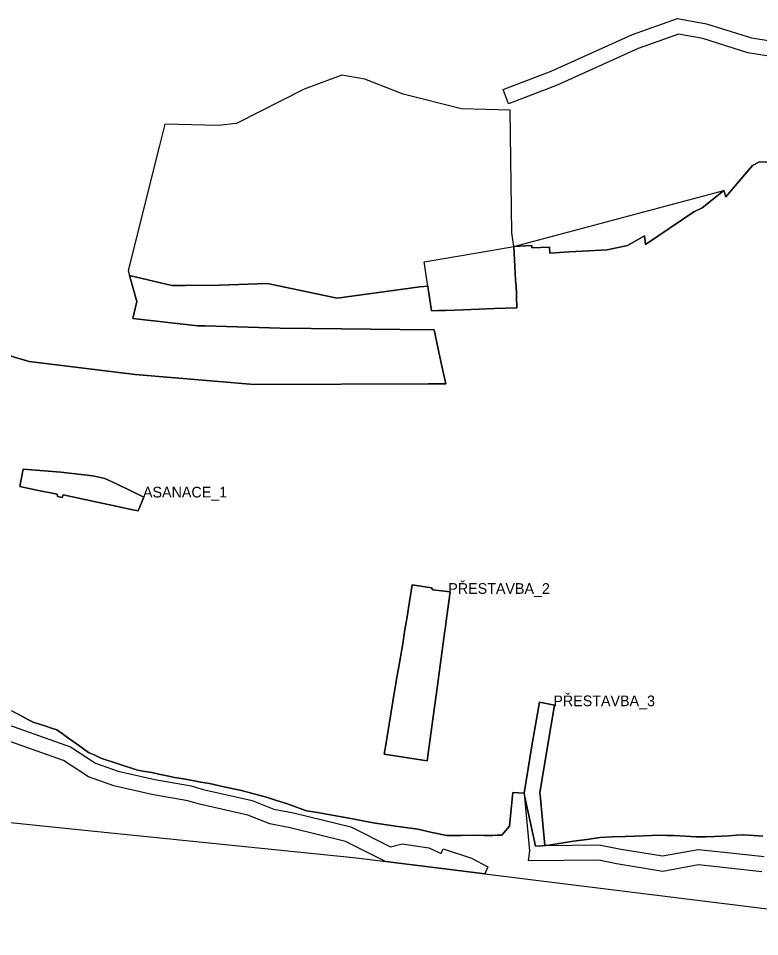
# Model space of a CAD drawing. Extents: x -521621 to -516761, y -1190184 to -1184927.
# Drawn here: x -519643 to -519157, y -1187565 to -1186963 of the extents above; entities that cross this region are included whole.
import ezdxf

# ---------------------------------------------------------------- set-up
doc = ezdxf.new("R2010")
doc.units = 0
for name, color, linetype in [('asanace_n', 7, 'Continuous'), ('hran_SZUO_P-s', 7, 'Continuous'), ('HZU_P_s', 7, 'Continuous'), ('Implicitní', 7, 'Continuous'), ('prestavba_n', 7, 'Continuous'), ('zastavitelne plochy', 7, 'Continuous')]:
    doc.layers.add(name, color=color, linetype=linetype)

msp = doc.modelspace()

# ---------------------------------------------------------------- linework, layer by layer
at = {"layer": 'asanace_n'}
msp.add_lwpolyline([(-519640.08, -1187258.64), (-519642.17, -1187270.06), (-519631.16, -1187272.32), (-519617.71, -1187275.08), (-519617.55, -1187276.62), (-519614.54, -1187277.08), (-519613.85, -1187275.54), (-519596.49, -1187279.24), (-519581.23, -1187282.49), (-519568.13, -1187285.28), (-519564.62, -1187286.03), (-519560.92, -1187276.93), (-519578.86, -1187268.28), (-519586.38, -1187264.66), (-519594.25, -1187262.96), (-519615.32, -1187260.57), (-519640.08, -1187258.64)], dxfattribs=at)
at = {"layer": 'hran_SZUO_P-s'}
for points in [[(-519157.33, -1187057.16), (-519161.95, -1187059.54)], [(-519095.24, -1187058.86), (-519157.33, -1187057.16)], [(-519161.95, -1187059.54), (-519179.53, -1187080.02)], [(-519180.77, -1187076), (-519188.69, -1187082.32)], [(-519179.53, -1187080.02), (-519180.77, -1187076)], [(-519194.92, -1187087.29), (-519200.56, -1187089.87)], [(-519188.69, -1187082.32), (-519194.92, -1187087.29)], [(-519200.56, -1187089.87), (-519232.12, -1187111.29)], [(-519232.7, -1187105.55), (-519243.91, -1187111.93)], [(-519232.12, -1187111.29), (-519232.7, -1187105.55)], [(-519306.72, -1187112.05), (-519318.38, -1187112.72)], [(-519318.38, -1187112.72), (-519317.33, -1187134.43)], [(-519306.63, -1187113.6), (-519306.72, -1187112.05)], [(-519295.05, -1187113.11), (-519306.63, -1187113.6)], [(-519294.77, -1187116.93), (-519295.05, -1187113.11)], [(-519282.06, -1187116.19), (-519294.77, -1187116.93)], [(-519269.34, -1187115.44), (-519282.06, -1187116.19)], [(-519257.18, -1187114.73), (-519269.34, -1187115.44)], [(-519243.91, -1187111.93), (-519257.18, -1187114.73)], [(-519542.51, -1187138.24), (-519570.28, -1187131.58)], [(-519570.28, -1187131.58), (-519565.59, -1187148.78)], [(-519317.33, -1187134.43), (-519317.16, -1187136.78), (-519316.98, -1187139.13)], [(-519533.88, -1187138.14), (-519542.51, -1187138.24)], [(-519511.41, -1187137.88), (-519533.88, -1187138.14)], [(-519479.95, -1187136.97), (-519511.41, -1187137.88)], [(-519439.45, -1187145.43), (-519479.95, -1187136.97)], [(-519379.97, -1187139), (-519434.32, -1187146.5)], [(-519374.79, -1187138.62), (-519379.97, -1187139)], [(-519373.47, -1187147.63), (-519374.79, -1187138.62)], [(-519316.98, -1187139.13), (-519316.87, -1187140.66), (-519316.76, -1187142.18)], [(-519434.32, -1187146.5), (-519439.45, -1187145.43)], [(-519316.76, -1187142.18), (-519316.68, -1187145.05), (-519316.6, -1187147.92)], [(-519565.59, -1187148.78), (-519568.17, -1187159.87)], [(-519372.41, -1187154.85), (-519373.47, -1187147.63)], [(-519331.04, -1187153.34), (-519341.19, -1187153.71)], [(-519316.47, -1187152.81), (-519323.75, -1187153.08), (-519331.04, -1187153.34)], [(-519316.6, -1187147.92), (-519316.54, -1187150.36)], [(-519316.54, -1187150.36), (-519316.47, -1187152.81)], [(-519367.87, -1187154.69), (-519372.41, -1187154.85)], [(-519363.32, -1187154.52), (-519367.87, -1187154.69)], [(-519351.35, -1187154.08), (-519357.33, -1187154.3), (-519363.32, -1187154.52)], [(-519341.19, -1187153.71), (-519351.35, -1187154.08)], [(-519568.17, -1187159.87), (-519525.62, -1187164.56)], [(-519525.62, -1187164.56), (-519520.78, -1187164.7)], [(-519520.78, -1187164.7), (-519471.58, -1187166.09)], [(-519636.11, -1187188.04), (-519691.98, -1187171.68)], [(-519471.58, -1187166.09), (-519431.2, -1187166.58)], [(-519431.2, -1187166.58), (-519393.07, -1187167.04)], [(-519393.07, -1187167.04), (-519370.6, -1187167.23)], [(-519370.6, -1187167.23), (-519367.71, -1187180.87)], [(-519367.71, -1187180.87), (-519366.84, -1187184.99)], [(-519566.51, -1187196.52), (-519636.11, -1187188.04)], [(-519366.84, -1187184.99), (-519365.76, -1187190.07)], [(-519365.76, -1187190.07), (-519363.08, -1187202.74)], [(-519488.58, -1187203.01), (-519566.51, -1187196.52)], [(-519374.38, -1187202.7), (-519488.58, -1187203.01)], [(-519363.08, -1187202.74), (-519374.38, -1187202.7)], [(-519647.92, -1187416.82), (-519644.14, -1187418.84), (-519640.35, -1187420.87)], [(-519640.35, -1187420.87), (-519636.92, -1187422.71), (-519633.49, -1187424.54)], [(-519633.49, -1187424.54), (-519629.29, -1187425.87), (-519625.09, -1187427.2)], [(-519625.09, -1187427.2), (-519621.5, -1187428.34), (-519617.9, -1187429.48)], [(-519617.9, -1187429.48), (-519614.38, -1187432.01), (-519610.86, -1187434.53)], [(-519610.86, -1187434.53), (-519607.28, -1187437.09), (-519603.7, -1187439.66)], [(-519603.7, -1187439.66), (-519600.46, -1187442.02), (-519597.22, -1187444.37)], [(-519597.22, -1187444.37), (-519593.13, -1187446.22), (-519589.04, -1187448.07)], [(-519589.04, -1187448.07), (-519577.04, -1187451.97), (-519565.04, -1187455.87)], [(-519565.04, -1187455.87), (-519560.34, -1187456.72), (-519555.63, -1187457.56)], [(-519555.63, -1187457.56), (-519551.2, -1187458.53), (-519546.76, -1187459.49)], [(-519546.76, -1187459.49), (-519543.79, -1187460.11), (-519540.81, -1187460.73)], [(-519540.81, -1187460.73), (-519534.91, -1187461.73), (-519529.01, -1187462.73)], [(-519529.01, -1187462.73), (-519523.46, -1187463.74), (-519517.9, -1187464.74)], [(-519517.9, -1187464.74), (-519507.45, -1187467.06), (-519496.99, -1187469.37)], [(-519496.99, -1187469.37), (-519488.81, -1187471.49), (-519480.63, -1187473.61)], [(-519321.33, -1187492.71), (-519320.25, -1187481.6), (-519319.17, -1187470.49)], [(-519319.17, -1187470.49), (-519315.42, -1187470.81), (-519311.66, -1187471.13)], [(-519311.66, -1187471.13), (-519311.4, -1187472.37), (-519311.13, -1187473.61)], [(-519480.63, -1187473.61), (-519474.07, -1187475.74), (-519467.51, -1187477.86)], [(-519467.51, -1187477.86), (-519460.92, -1187480.22), (-519454.32, -1187482.57)], [(-519311.13, -1187473.61), (-519307.7, -1187489.7), (-519304.26, -1187505.78)], [(-519454.32, -1187482.57), (-519447.14, -1187483.77), (-519439.96, -1187484.96)], [(-519439.96, -1187484.96), (-519425.26, -1187487.74), (-519410.56, -1187490.51)], [(-519410.56, -1187490.51), (-519395.98, -1187492.59), (-519381.4, -1187494.68)], [(-519381.4, -1187494.68), (-519371.91, -1187496.73), (-519362.42, -1187498.77)], [(-519326.38, -1187498.54), (-519323.86, -1187495.62)], [(-519323.86, -1187495.62), (-519321.33, -1187492.71)], [(-519362.42, -1187498.77), (-519353.05, -1187498.69)], [(-519353.05, -1187498.69), (-519343.67, -1187498.61)], [(-519343.67, -1187498.61), (-519337.96, -1187498.69), (-519332.25, -1187498.77)], [(-519332.25, -1187498.77), (-519329.32, -1187498.66), (-519326.38, -1187498.54)], [(-519295.55, -1187505.13), (-519287.41, -1187503.86), (-519279.26, -1187502.6)], [(-519279.26, -1187502.6), (-519270.6, -1187501.33), (-519261.94, -1187500.07)], [(-519261.94, -1187500.07), (-519253.7, -1187499.74)], [(-519253.7, -1187499.74), (-519245.46, -1187499.41)], [(-519245.46, -1187499.41), (-519239.43, -1187499.15), (-519233.4, -1187498.89)], [(-519233.4, -1187498.89), (-519228.23, -1187498.74), (-519223.06, -1187498.58)], [(-519223.06, -1187498.58), (-519218.25, -1187498.72), (-519213.43, -1187498.85)], [(-519213.43, -1187498.85), (-519206.12, -1187499.23), (-519198.82, -1187499.6)], [(-519198.82, -1187499.6), (-519192.88, -1187499.56), (-519186.93, -1187499.51)], [(-519186.93, -1187499.51), (-519182.2, -1187499.2), (-519177.46, -1187498.89)], [(-519177.46, -1187498.89), (-519172.56, -1187498.66), (-519167.66, -1187498.42)], [(-519167.66, -1187498.42), (-519161.43, -1187498.86), (-519155.19, -1187499.3)], [(-519304.26, -1187505.78), (-519299.91, -1187505.46)], [(-519299.91, -1187505.46), (-519295.55, -1187505.13)]]:
    msp.add_lwpolyline(points, dxfattribs=at)
at = {"layer": 'HZU_P_s'}
for p, q in [((-519161.95, -1187059.54), (-519157.33, -1187057.16)), ((-519157.33, -1187057.16), (-519095.24, -1187058.86)), ((-519179.53, -1187080.02), (-519161.95, -1187059.54)), ((-519188.69, -1187082.32), (-519180.77, -1187076)), ((-519180.77, -1187076), (-519179.53, -1187080.02)), ((-519200.56, -1187089.87), (-519194.92, -1187087.29)), ((-519194.92, -1187087.29), (-519188.69, -1187082.32)), ((-519232.12, -1187111.29), (-519200.56, -1187089.87)), ((-519243.91, -1187111.93), (-519232.7, -1187105.55)), ((-519232.7, -1187105.55), (-519232.12, -1187111.29)), ((-519318.38, -1187112.72), (-519306.72, -1187112.05)), ((-519317.33, -1187134.43), (-519318.38, -1187112.72)), ((-519306.72, -1187112.05), (-519306.63, -1187113.6)), ((-519306.63, -1187113.6), (-519295.05, -1187113.11)), ((-519295.05, -1187113.11), (-519294.77, -1187116.93)), ((-519294.77, -1187116.93), (-519282.06, -1187116.19)), ((-519282.06, -1187116.19), (-519269.34, -1187115.44)), ((-519269.34, -1187115.44), (-519257.18, -1187114.73)), ((-519257.18, -1187114.73), (-519243.91, -1187111.93)), ((-519565.59, -1187148.78), (-519570.28, -1187131.58)), ((-519570.28, -1187131.58), (-519542.51, -1187138.24)), ((-519317.16, -1187136.78), (-519317.33, -1187134.43)), ((-519542.51, -1187138.24), (-519533.88, -1187138.14)), ((-519533.88, -1187138.14), (-519511.41, -1187137.88)), ((-519511.41, -1187137.88), (-519479.95, -1187136.97)), ((-519479.95, -1187136.97), (-519439.45, -1187145.43)), ((-519434.32, -1187146.5), (-519379.97, -1187139)), ((-519379.97, -1187139), (-519374.79, -1187138.62)), ((-519374.79, -1187138.62), (-519373.47, -1187147.63)), ((-519439.45, -1187145.43), (-519434.32, -1187146.5)), ((-519568.17, -1187159.87), (-519565.59, -1187148.78)), ((-519373.47, -1187147.63), (-519372.41, -1187154.85)), ((-519316.47, -1187152.81), (-519316.54, -1187150.36)), ((-519525.62, -1187164.56), (-519568.17, -1187159.87)), ((-519520.78, -1187164.7), (-519525.62, -1187164.56)), ((-519471.58, -1187166.09), (-519520.78, -1187164.7)), ((-519691.98, -1187171.68), (-519636.11, -1187188.04)), ((-519431.2, -1187166.58), (-519471.58, -1187166.09)), ((-519393.07, -1187167.04), (-519431.2, -1187166.58)), ((-519370.6, -1187167.23), (-519393.07, -1187167.04)), ((-519367.71, -1187180.87), (-519370.6, -1187167.23)), ((-519366.84, -1187184.99), (-519367.71, -1187180.87)), ((-519636.11, -1187188.04), (-519566.51, -1187196.52)), ((-519365.76, -1187190.07), (-519366.84, -1187184.99)), ((-519363.08, -1187202.74), (-519365.76, -1187190.07)), ((-519566.51, -1187196.52), (-519488.58, -1187203.01)), ((-519488.58, -1187203.01), (-519374.38, -1187202.7)), ((-519374.38, -1187202.7), (-519363.08, -1187202.74)), ((-519640.35, -1187420.87), (-519644.14, -1187418.84)), ((-519636.92, -1187422.71), (-519640.35, -1187420.87)), ((-519633.49, -1187424.54), (-519636.92, -1187422.71)), ((-519629.29, -1187425.87), (-519633.49, -1187424.54)), ((-519625.09, -1187427.2), (-519629.29, -1187425.87)), ((-519621.5, -1187428.34), (-519625.09, -1187427.2)), ((-519319.17, -1187470.49), (-519320.25, -1187481.6)), ((-519315.42, -1187470.81), (-519319.17, -1187470.49)), ((-519311.66, -1187471.13), (-519315.42, -1187470.81)), ((-519311.4, -1187472.37), (-519311.66, -1187471.13)), ((-519311.13, -1187473.61), (-519311.4, -1187472.37)), ((-519307.7, -1187489.7), (-519311.13, -1187473.61)), ((-519304.26, -1187505.78), (-519307.7, -1187489.7)), ((-519362.42, -1187498.77), (-519371.91, -1187496.73)), ((-519353.05, -1187498.69), (-519362.42, -1187498.77)), ((-519343.67, -1187498.61), (-519353.05, -1187498.69)), ((-519337.96, -1187498.69), (-519343.67, -1187498.61)), ((-519332.25, -1187498.77), (-519337.96, -1187498.69)), ((-519329.32, -1187498.66), (-519332.25, -1187498.77)), ((-519279.26, -1187502.6), (-519287.41, -1187503.86)), ((-519270.6, -1187501.33), (-519279.26, -1187502.6)), ((-519261.94, -1187500.07), (-519270.6, -1187501.33)), ((-519253.7, -1187499.74), (-519261.94, -1187500.07)), ((-519245.46, -1187499.41), (-519253.7, -1187499.74)), ((-519239.43, -1187499.15), (-519245.46, -1187499.41)), ((-519233.4, -1187498.89), (-519239.43, -1187499.15)), ((-519228.23, -1187498.74), (-519233.4, -1187498.89)), ((-519223.06, -1187498.58), (-519228.23, -1187498.74)), ((-519218.25, -1187498.72), (-519223.06, -1187498.58)), ((-519213.43, -1187498.85), (-519218.25, -1187498.72)), ((-519206.12, -1187499.23), (-519213.43, -1187498.85)), ((-519198.82, -1187499.6), (-519206.12, -1187499.23)), ((-519192.88, -1187499.56), (-519198.82, -1187499.6)), ((-519186.93, -1187499.51), (-519192.88, -1187499.56)), ((-519182.2, -1187499.2), (-519186.93, -1187499.51)), ((-519177.46, -1187498.89), (-519182.2, -1187499.2)), ((-519172.56, -1187498.66), (-519177.46, -1187498.89)), ((-519167.66, -1187498.42), (-519172.56, -1187498.66)), ((-519161.43, -1187498.86), (-519167.66, -1187498.42)), ((-519155.19, -1187499.3), (-519161.43, -1187498.86)), ((-519299.91, -1187505.46), (-519304.26, -1187505.78)), ((-519295.55, -1187505.13), (-519299.91, -1187505.46)), ((-519287.41, -1187503.86), (-519295.55, -1187505.13))]:
    msp.add_line(p, q, dxfattribs=at)
for points in [[(-519316.98, -1187139.13), (-519317.16, -1187136.78)], [(-519316.87, -1187140.66), (-519316.98, -1187139.13)], [(-519316.76, -1187142.18), (-519316.87, -1187140.66)], [(-519316.6, -1187147.92), (-519316.68, -1187145.05), (-519316.76, -1187142.18)], [(-519341.19, -1187153.71), (-519331.04, -1187153.34), (-519323.75, -1187153.08), (-519316.47, -1187152.81)], [(-519316.54, -1187150.36), (-519316.6, -1187147.92)], [(-519372.41, -1187154.85), (-519367.87, -1187154.69)], [(-519367.87, -1187154.69), (-519363.32, -1187154.52)], [(-519363.32, -1187154.52), (-519357.33, -1187154.3)], [(-519357.33, -1187154.3), (-519351.35, -1187154.08)], [(-519351.35, -1187154.08), (-519341.19, -1187153.71)], [(-519617.9, -1187429.48), (-519621.5, -1187428.34)], [(-519610.86, -1187434.53), (-519614.38, -1187432.01), (-519617.9, -1187429.48)], [(-519603.7, -1187439.66), (-519607.28, -1187437.09), (-519610.86, -1187434.53)], [(-519597.22, -1187444.37), (-519600.46, -1187442.02), (-519603.7, -1187439.66)], [(-519589.04, -1187448.07), (-519593.13, -1187446.22), (-519597.22, -1187444.37)], [(-519565.04, -1187455.87), (-519577.04, -1187451.97), (-519589.04, -1187448.07)], [(-519555.63, -1187457.56), (-519560.34, -1187456.72), (-519565.04, -1187455.87)], [(-519546.76, -1187459.49), (-519551.2, -1187458.53), (-519555.63, -1187457.56)], [(-519540.81, -1187460.73), (-519543.79, -1187460.11), (-519546.76, -1187459.49)], [(-519529.01, -1187462.73), (-519534.91, -1187461.73), (-519540.81, -1187460.73)], [(-519517.9, -1187464.74), (-519523.46, -1187463.74), (-519529.01, -1187462.73)], [(-519496.99, -1187469.37), (-519507.45, -1187467.06), (-519517.9, -1187464.74)], [(-519480.63, -1187473.61), (-519488.81, -1187471.49), (-519496.99, -1187469.37)], [(-519467.51, -1187477.86), (-519474.07, -1187475.74), (-519480.63, -1187473.61)], [(-519454.32, -1187482.57), (-519460.92, -1187480.22), (-519467.51, -1187477.86)], [(-519439.96, -1187484.96), (-519447.14, -1187483.77), (-519454.32, -1187482.57)], [(-519320.25, -1187481.6), (-519321.33, -1187492.71)], [(-519410.56, -1187490.51), (-519425.26, -1187487.74), (-519439.96, -1187484.96)], [(-519381.4, -1187494.68), (-519395.98, -1187492.59), (-519410.56, -1187490.51)], [(-519371.91, -1187496.73), (-519381.4, -1187494.68)], [(-519323.86, -1187495.62), (-519326.38, -1187498.54)], [(-519321.33, -1187492.71), (-519323.86, -1187495.62)], [(-519326.38, -1187498.54), (-519329.32, -1187498.66)]]:
    msp.add_lwpolyline(points, dxfattribs=at)
at = {"layer": 'Implicitní'}
for p, q in [((-519377.12, -1187122.72), (-519333.59, -1187115.31)), ((-519333.59, -1187115.31), (-519318.38, -1187112.72)), ((-519318.38, -1187112.72), (-519317.33, -1187134.43)), ((-519374.79, -1187138.62), (-519377.12, -1187122.72)), ((-519317.33, -1187134.43), (-519316.98, -1187139.13)), ((-519373.47, -1187147.63), (-519374.79, -1187138.62)), ((-519316.98, -1187139.13), (-519316.76, -1187142.18)), ((-519316.76, -1187142.18), (-519316.6, -1187147.92)), ((-519372.42, -1187154.83), (-519373.47, -1187147.63)), ((-519331.04, -1187153.34), (-519351.35, -1187154.08)), ((-519316.47, -1187152.81), (-519331.04, -1187153.34)), ((-519316.6, -1187147.92), (-519316.47, -1187152.81)), ((-519372.41, -1187154.85), (-519372.42, -1187154.83)), ((-519363.32, -1187154.52), (-519372.41, -1187154.85)), ((-519351.35, -1187154.08), (-519363.32, -1187154.52)), ((-519386.81, -1187345.32), (-519385.08, -1187334.48)), ((-519385.08, -1187334.48), (-519372.33, -1187336.38)), ((-519372.33, -1187336.38), (-519371.56, -1187337.62)), ((-519371.56, -1187337.62), (-519360.16, -1187339.01)), ((-519360.16, -1187339.01), (-519362.97, -1187359.69)), ((-519387.49, -1187349.53), (-519386.81, -1187345.32)), ((-519388.2, -1187354.01), (-519387.49, -1187349.53)), ((-519390, -1187365.25), (-519388.2, -1187354.01)), ((-519363.29, -1187362.04), (-519363.84, -1187366.05)), ((-519362.97, -1187359.69), (-519363.29, -1187362.04)), ((-519391.27, -1187373.19), (-519390, -1187365.25)), ((-519363.84, -1187366.05), (-519368.47, -1187400.46)), ((-519394.08, -1187389.28), (-519391.27, -1187373.19)), ((-519395.24, -1187395.97), (-519394.08, -1187389.28)), ((-519649.58, -1187426.2), (-519608.99, -1187440.55)), ((-519613.48, -1187449.57), (-519652.56, -1187435.75)), ((-519608.99, -1187440.55), (-519592.63, -1187451.35)), ((-519597.12, -1187460.37), (-519613.48, -1187449.57)), ((-519592.63, -1187451.35), (-519577.81, -1187456.6)), ((-519580.58, -1187466.23), (-519597.12, -1187460.37)), ((-519577.81, -1187456.6), (-519553.74, -1187462)), ((-519555.72, -1187471.8), (-519580.58, -1187466.23)), ((-519553.74, -1187462), (-519529.82, -1187466.32)), ((-519529.82, -1187466.32), (-519521.95, -1187468.64)), ((-519532.13, -1187476.06), (-519555.72, -1187471.8)), ((-519521.95, -1187468.64), (-519489.85, -1187475.89)), ((-519790.94, -1187475.66), (-519606.2, -1187494.58)), ((-519524.47, -1187478.32), (-519532.13, -1187476.06)), ((-519492.79, -1187485.48), (-519524.47, -1187478.32)), ((-519489.85, -1187475.89), (-519475.65, -1187481.45)), ((-519475.65, -1187481.45), (-519462.84, -1187483.92)), ((-519462.84, -1187483.92), (-519425.34, -1187493.18)), ((-519478.44, -1187491.1), (-519492.79, -1187485.48)), ((-519606.2, -1187494.58), (-519421.47, -1187513.5)), ((-519464.99, -1187493.69), (-519478.44, -1187491.1)), ((-519428.83, -1187502.62), (-519464.99, -1187493.69)), ((-519425.34, -1187493.18), (-519399.26, -1187506.29)), ((-519402.49, -1187515.86), (-519428.83, -1187502.62)), ((-519399.26, -1187506.29), (-519391.7, -1187504.29)), ((-519391.7, -1187504.29), (-519374.11, -1187506.76)), ((-519374.11, -1187506.76), (-519366.08, -1187510.61)), ((-519366.08, -1187510.61), (-519364.69, -1187507.53)), ((-519364.69, -1187507.53), (-519346.17, -1187513.55)), ((-519421.47, -1187513.5), (-519337.51, -1187523.93)), ((-519346.17, -1187513.55), (-519335.52, -1187519.26)), ((-519337.51, -1187523.93), (-519402.49, -1187515.86)), ((-519335.52, -1187519.26), (-519337.51, -1187523.93)), ((-519337.51, -1187523.93), (-519310.89, -1187527.24)), ((-519310.89, -1187527.24), (-519006.29, -1187565.08))]:
    msp.add_line(p, q, dxfattribs=at)
for points in [[(-519145.9, -1186988.7), (-519165.02, -1186985.57), (-519194.65, -1186976.29), (-519210.41, -1186973.39), (-519237.02, -1186982.89), (-519290.02, -1187006.82), (-519321.89, -1187019.12), (-519325.49, -1187009.79), (-519293.88, -1186997.59), (-519240.76, -1186973.61), (-519211.24, -1186963.07), (-519192.24, -1186966.57), (-519162.71, -1186975.82), (-519146.1, -1186978.53)], [(-519368.47, -1187400.46), (-519372.15, -1187427.24), (-519375.25, -1187449.81), (-519403.45, -1187445.56), (-519402.62, -1187440.63), (-519396.68, -1187404.21), (-519395.59, -1187397.94)], [(-519395.59, -1187397.94), (-519395.24, -1187395.97)], [(-519155.94, -1187522.52), (-519175.44, -1187520.4), (-519197.31, -1187518.08), (-519220.81, -1187522.3), (-519251.1, -1187517.44), (-519262.71, -1187515.06), (-519308.73, -1187515.41), (-519307.91, -1187508.76), (-519311.13, -1187473.61), (-519311.66, -1187471.13), (-519306.32, -1187438.74), (-519301.65, -1187411.41), (-519291.84, -1187413.36), (-519296.46, -1187440.4), (-519301.49, -1187470.89), (-519301.23, -1187472.1), (-519298.18, -1187505.33), (-519262.49, -1187504.9), (-519249.3, -1187507.6), (-519220.9, -1187512.16), (-519197.67, -1187507.99), (-519174.37, -1187510.46), (-519154.46, -1187512.62)]]:
    msp.add_lwpolyline(points, dxfattribs=at)
for points in [[(-519257.18, -1187114.73), (-519269.34, -1187115.44), (-519282.06, -1187116.19), (-519294.77, -1187116.93), (-519295.05, -1187113.11), (-519306.63, -1187113.6), (-519306.72, -1187112.05), (-519318.38, -1187112.72), (-519180.77, -1187076), (-519188.69, -1187082.32), (-519194.92, -1187087.29), (-519200.56, -1187089.87), (-519232.12, -1187111.29), (-519232.7, -1187105.55), (-519243.91, -1187111.93)], [(-519640.08, -1187258.64), (-519615.32, -1187260.57), (-519594.25, -1187262.96), (-519586.38, -1187264.66), (-519578.86, -1187268.28), (-519560.92, -1187276.93), (-519564.62, -1187286.03), (-519568.13, -1187285.28), (-519581.23, -1187282.49), (-519596.49, -1187279.24), (-519613.85, -1187275.54), (-519614.54, -1187277.08), (-519617.55, -1187276.62), (-519617.71, -1187275.08), (-519631.16, -1187272.32), (-519642.17, -1187270.06)]]:
    msp.add_lwpolyline(points, close=True, dxfattribs=at)
at = {"layer": 'prestavba_n'}
for points in [[(-519368.47, -1187400.46), (-519363.84, -1187366.05), (-519363.29, -1187362.04), (-519362.97, -1187359.69), (-519360.16, -1187339.01), (-519371.56, -1187337.62), (-519372.33, -1187336.38), (-519385.08, -1187334.48), (-519386.81, -1187345.32), (-519387.49, -1187349.53), (-519388.2, -1187354.01), (-519390, -1187365.25), (-519391.27, -1187373.19), (-519394.08, -1187389.28), (-519395.24, -1187395.97), (-519395.59, -1187397.94), (-519396.68, -1187404.21), (-519402.62, -1187440.63), (-519403.45, -1187445.56), (-519375.25, -1187449.81), (-519372.15, -1187427.24), (-519368.47, -1187400.46)], [(-519311.4, -1187472.37), (-519311.13, -1187473.61), (-519307.7, -1187489.7), (-519304.26, -1187505.78), (-519299.91, -1187505.46), (-519298.18, -1187505.33), (-519301.23, -1187472.1), (-519301.49, -1187470.89), (-519296.46, -1187440.4), (-519291.84, -1187413.36), (-519301.65, -1187411.41), (-519306.32, -1187438.74), (-519311.66, -1187471.13), (-519311.4, -1187472.37)]]:
    msp.add_lwpolyline(points, dxfattribs=at)
at = {"layer": 'zastavitelne plochy'}
msp.add_lwpolyline([(-519318.38, -1187112.72), (-519319.82, -1187103.73), (-519320.86, -1187023.21), (-519352.73, -1187022.37), (-519390.87, -1187012.81), (-519416.18, -1187002.97), (-519431.08, -1187000.25), (-519455.92, -1187009.53), (-519500.2, -1187031.95), (-519512.14, -1187033.24), (-519547.18, -1187032.53), (-519550.67, -1187046.48), (-519571.17, -1187128.34), (-519570.28, -1187131.58), (-519542.51, -1187138.24), (-519533.88, -1187138.14), (-519511.41, -1187137.88), (-519479.95, -1187136.97), (-519439.45, -1187145.43), (-519434.32, -1187146.5), (-519379.97, -1187139), (-519374.79, -1187138.62), (-519377.12, -1187122.72), (-519333.59, -1187115.31), (-519318.38, -1187112.72)], dxfattribs=at)

# ---------------------------------------------------------------- texts
at = {"layer": 'asanace_n'}
msp.add_text('ASANACE_1', height=7, dxfattribs=at).set_placement((-519561.48, -1187277.16))
at = {"layer": 'prestavba_n'}
for s, p in [('PŘESTAVBA_2', (-519361.37, -1187340.35)), ('PŘESTAVBA_3', (-519292.51, -1187414))]:
    msp.add_text(s, height=7, dxfattribs=at).set_placement(p)

doc.saveas('drawing.dxf')
